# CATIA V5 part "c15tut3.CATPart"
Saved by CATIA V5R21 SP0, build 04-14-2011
Part number: Part1
Bounding box of the stored display mesh (mm): x -75 to 75, y -40 to 40, z 0 to 5
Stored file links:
  D:\CATIA V5R21 E-RESOURCES\CATIA-V5R21\catia-v5r21-prt\c15-catia-v5r20-prt\c15-catia-v5r21-tut03.CATPart
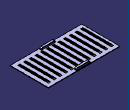
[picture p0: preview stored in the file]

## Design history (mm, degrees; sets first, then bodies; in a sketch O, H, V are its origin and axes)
SheetMetalParameters1: Thickness 1, BendRadius 2, KFactor 0.400515 {= log(min(100,max(20*SheetMetalParameters1.BendRadius,SheetMetalParameters1.Thickness)/SheetMetalParameters1.Thickness))/log(100)/2}, ReliefRadialLength 1, ReliefAxialLength 2, MinimumBendRadius 0
Body1 (main body)
  Sketch1 on xy-plane, origin (0, 0, 0), H (1, 0, 0), V (0, 1, 0)
    line L1 (75, 40) -> (75, -40)
    line L2 (75, -40) -> (-75, -40)
    line L3 (-75, -40) -> (-75, 40)
    line L4 (-75, 40) -> (75, 40)
    length L4 = 150
    length L1 = 80
    vertical: L1 V, L3 V
    horizontal: L2 H, L4 H
    equidistance: L1 L3 O, L2 L4 O
  Wall1: Thickness 1, Profile Sketch1
  Sketch2 on face of Wall1, origin (0, 0, 0), H (1, 0, 0), V (0, 1, 0)
    line L1 (64.5, 30) -> (67, 30)
    line L2 (67, 30) -> (67, -30)
    line L3 (67, -30) -> (64.5, -30)
    line L4 (64.5, -30) -> (64.5, 30)
    reference projected line E1 (75, 40) -> (75, -40) from edge [face of Wall1 | face of Wall1]
    reference projected line E2 (-75, 40) -> (75, 40) from edge [face of Wall1 | face of Wall1]
    length L2 = 60
    distance L2 L4 = 2.5
    distance E1 L2 = 8
    distance L1 E2 = 10
    horizontal: L1 H, L3 H
    vertical: L2 V, L4 V
  d_Stamp1: NewRoot_AttribNormalisation "No Standard", Stamp_FilletRadius 2
  RectPattern1: of d_Stamp1, direction 1 instances 12, spacing 12, along face of Wall1 reversed
  Sketch3 on face of Wall1, origin (0, 0, 0), H (1, 0, 0), V (0, -1, 0)
    point P1 (0, 36.5)
    reference projected line E1 (75, 40) -> (75, -40) from edge [face of Wall1 | face of Wall1]
    reference projected line E2 (-75, 40) -> (75, 40) from edge [face of Wall1 | face of Wall1]
    distance P1 E1 = 75
    distance P1 E2 = 3.5
  Sketch4 on face of Wall1, origin (0, -36.5, 0), H (1, 0, 0), V (0, 1, 0)
    point P1 (0, 0)
    reference projected point E1 (0, 0) from Sketch3.P1
    coincidence: E1 P1
  d_Stamp2: NewRoot_AttribNormalisation "No Standard", Stamp_FilletRadius 0.5
  SHM_Mirror1: MirroringPlane zx-plane, ObjectToMirror d_Stamp2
